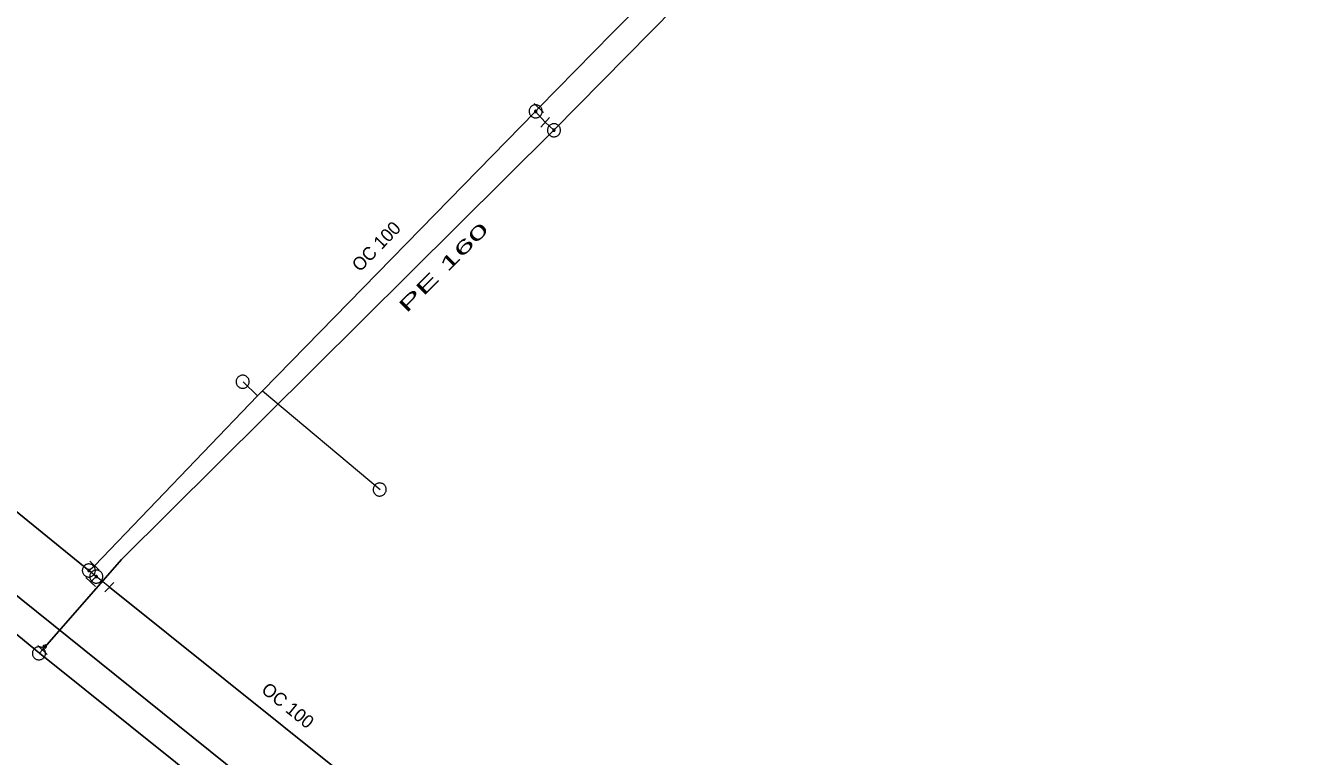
# Model space of a CAD drawing. Extents: x -807203 to -805207, y -993656 to -992505.
# Drawn here: x -806438 to -806339.8, y -992895 to -992839.2 of the extents above; entities that cross this region are included whole.
import ezdxf

# ---------------------------------------------------------------- set-up
doc = ezdxf.new("R2010")
doc.units = 0
doc.header["$LTSCALE"] = 0.4
for name, color, linetype, lineweight in [('1', 7, 'Continuous', 13), ('13', 7, 'Continuous', 13), ('14', 7, 'Continuous', 25), ('17', 7, 'Continuous', 25), ('23', 7, 'Continuous', 13), ('34', 7, 'Continuous', 13), ('47', 7, 'Continuous', 13)]:
    doc.layers.add(name, color=color, linetype=linetype, lineweight=lineweight)

msp = doc.modelspace()

# ---------------------------------------------------------------- linework, layer by layer
at = {"layer": '13'}
for p, q in [((-806420.276, -992867.469), (-806421.386, -992866.4)), ((-806419.892, -992867.102), (-806410.923, -992874.624))]:
    msp.add_line(p, q, dxfattribs=at)
at = {"layer": '14', "lineweight": 13}
for p, q in [((-806398.804, -992845.506), (-806399.05, -992845.763)), ((-806433.161, -992880.802), (-806432.726, -992880.435)), ((-806432.592, -992881.266), (-806433.161, -992880.802)), ((-806432.592, -992881.266), (-806433.026, -992881.683)), ((-806431.594, -992882.078), (-806432.592, -992881.266)), ((-806436.941, -992887.123), (-806436.699, -992886.863))]:
    msp.add_line(p, q, dxfattribs=at)
at = {"layer": '14'}
msp.add_lwpolyline([(-806439.491, -992882.042), (-806390.48, -992921.449), (-806366.285, -992941.529), (-806350.28, -992945.949), (-806336.559, -992959.469), (-806296.91, -993006.629), (-806254.43, -993051.92)], dxfattribs=at)
at = {"layer": '17'}
for p, q in [((-806398.321, -992846.589), (-806399.05, -992845.763)), ((-806397.651, -992847.204), (-806398.321, -992846.589))]:
    msp.add_line(p, q, dxfattribs=at)
for points in [[(-806521.443, -992807.149), (-806519.338, -992810.368), (-806510.309, -992820.324), (-806509.868, -992820.798), (-806504.706, -992825.727), (-806500.491, -992829.715), (-806490.227, -992839.136), (-806481.238, -992847.311), (-806469.245, -992858.467), (-806459.171, -992867.71), (-806448.037, -992877.98), (-806436.941, -992887.123)], [(-806361.995, -992808.32), (-806393.217, -992839.791), (-806398.804, -992845.506)], [(-806397.651, -992847.204), (-806360.609, -992809.633), (-806361.818, -992808.52)], [(-806433.161, -992880.802), (-806443.471, -992872.44), (-806476.543, -992840.262)], [(-806399.05, -992845.763), (-806419.892, -992867.102), (-806420.276, -992867.469), (-806432.726, -992880.435)], [(-806436.699, -992886.863), (-806430.658, -992879.958), (-806397.651, -992847.204)], [(-806388.717, -992915.707), (-806398.552, -992908.37), (-806405.099, -992903.291), (-806431.594, -992882.078)], [(-806436.941, -992887.123), (-806426.546, -992895.427), (-806410.702, -992908.298), (-806403.285, -992914.215), (-806402.857, -992914.754), (-806391.193, -992925.692), (-806378.734, -992937.224), (-806370.048, -992945.254), (-806362.636, -992951.833), (-806355.477, -992958.243), (-806351.647, -992962.778), (-806345.155, -992970.14), (-806339.761, -992976.258), (-806328.906, -992988.261), (-806292.949, -993029.767), (-806263.022, -993062.39), (-806260.066, -993064.828)]]:
    msp.add_lwpolyline(points, dxfattribs=at)
at = {"layer": '23'}
msp.add_line((-806436.462, -992886.678), (-806436.614, -992886.553), dxfattribs=at)
for points in [[(-806421.054, -992866.743), (-806421.019, -992866.702), (-806420.99, -992866.659), (-806420.966, -992866.613), (-806420.946, -992866.564), (-806420.932, -992866.515), (-806420.923, -992866.462), (-806420.919, -992866.41), (-806420.921, -992866.359), (-806420.927, -992866.307), (-806420.94, -992866.256), (-806420.957, -992866.206), (-806420.98, -992866.158), (-806421.007, -992866.114), (-806421.039, -992866.074), (-806421.075, -992866.036), (-806421.116, -992866.001), (-806421.158, -992865.972), (-806421.206, -992865.947), (-806421.252, -992865.928), (-806421.303, -992865.912), (-806421.356, -992865.904), (-806421.408, -992865.9), (-806421.461, -992865.902), (-806421.512, -992865.908), (-806421.562, -992865.921), (-806421.612, -992865.94), (-806421.658, -992865.962), (-806421.703, -992865.99), (-806421.744, -992866.022), (-806421.782, -992866.058), (-806421.816, -992866.097), (-806421.846, -992866.141), (-806421.871, -992866.187), (-806421.891, -992866.235), (-806421.904, -992866.285), (-806421.913, -992866.337), (-806421.918, -992866.389), (-806421.916, -992866.442), (-806421.909, -992866.494)], [(-806421.206, -992865.947), (-806421.252, -992865.928), (-806421.303, -992865.912), (-806421.356, -992865.904), (-806421.408, -992865.9), (-806421.461, -992865.902), (-806421.512, -992865.908), (-806421.562, -992865.921), (-806421.612, -992865.94), (-806421.658, -992865.962), (-806421.703, -992865.99), (-806421.744, -992866.022), (-806421.782, -992866.058), (-806421.816, -992866.097), (-806421.846, -992866.141), (-806421.871, -992866.187), (-806421.891, -992866.235), (-806421.904, -992866.285), (-806421.913, -992866.337), (-806421.918, -992866.389), (-806421.916, -992866.442), (-806421.909, -992866.494), (-806421.897, -992866.544), (-806421.879, -992866.593), (-806421.857, -992866.64), (-806421.828, -992866.685), (-806421.796, -992866.726), (-806421.761, -992866.764), (-806421.72, -992866.797), (-806421.677, -992866.827), (-806421.631, -992866.852), (-806421.582, -992866.871), (-806421.532, -992866.886), (-806421.481, -992866.896), (-806421.428, -992866.899), (-806421.377, -992866.898), (-806421.325, -992866.891), (-806421.273, -992866.879), (-806421.224, -992866.861), (-806421.177, -992866.838)], [(-806421.909, -992866.494), (-806421.897, -992866.544), (-806421.879, -992866.593), (-806421.857, -992866.64), (-806421.828, -992866.685), (-806421.796, -992866.726), (-806421.761, -992866.764), (-806421.72, -992866.797), (-806421.677, -992866.827), (-806421.631, -992866.852), (-806421.582, -992866.871), (-806421.532, -992866.886), (-806421.481, -992866.896), (-806421.428, -992866.899), (-806421.377, -992866.898), (-806421.325, -992866.891), (-806421.273, -992866.879), (-806421.224, -992866.861), (-806421.177, -992866.838), (-806421.133, -992866.809), (-806421.092, -992866.778), (-806421.054, -992866.743), (-806421.019, -992866.702), (-806420.99, -992866.659), (-806420.966, -992866.613), (-806420.946, -992866.564), (-806420.932, -992866.515), (-806420.923, -992866.462), (-806420.919, -992866.41), (-806420.921, -992866.359), (-806420.927, -992866.307), (-806420.94, -992866.256), (-806420.957, -992866.206), (-806420.98, -992866.158), (-806421.007, -992866.114), (-806421.039, -992866.074), (-806421.075, -992866.036), (-806421.116, -992866.001), (-806421.158, -992865.972), (-806421.206, -992865.947)], [(-806421.177, -992866.838), (-806421.133, -992866.809), (-806421.092, -992866.778), (-806421.054, -992866.743)], [(-806410.591, -992874.967), (-806410.556, -992874.926), (-806410.527, -992874.883), (-806410.503, -992874.837), (-806410.483, -992874.788), (-806410.469, -992874.739), (-806410.46, -992874.686), (-806410.456, -992874.634), (-806410.458, -992874.583), (-806410.464, -992874.531), (-806410.477, -992874.48), (-806410.494, -992874.43), (-806410.517, -992874.382), (-806410.544, -992874.338), (-806410.576, -992874.298), (-806410.612, -992874.26), (-806410.653, -992874.225), (-806410.695, -992874.196), (-806410.743, -992874.171), (-806410.789, -992874.152), (-806410.84, -992874.136), (-806410.893, -992874.128), (-806410.945, -992874.124), (-806410.998, -992874.126), (-806411.049, -992874.132), (-806411.099, -992874.145), (-806411.149, -992874.164), (-806411.195, -992874.186), (-806411.24, -992874.214), (-806411.281, -992874.246), (-806411.319, -992874.282), (-806411.353, -992874.321), (-806411.383, -992874.365), (-806411.408, -992874.411), (-806411.428, -992874.459), (-806411.441, -992874.509), (-806411.45, -992874.561), (-806411.455, -992874.613), (-806411.453, -992874.666), (-806411.446, -992874.718)], [(-806410.743, -992874.171), (-806410.789, -992874.152), (-806410.84, -992874.136), (-806410.893, -992874.128), (-806410.945, -992874.124), (-806410.998, -992874.126), (-806411.049, -992874.132), (-806411.099, -992874.145), (-806411.149, -992874.164), (-806411.195, -992874.186), (-806411.24, -992874.214), (-806411.281, -992874.246), (-806411.319, -992874.282), (-806411.353, -992874.321), (-806411.383, -992874.365), (-806411.408, -992874.411), (-806411.428, -992874.459), (-806411.441, -992874.509), (-806411.45, -992874.561), (-806411.455, -992874.613), (-806411.453, -992874.666), (-806411.446, -992874.718), (-806411.434, -992874.768), (-806411.416, -992874.817), (-806411.394, -992874.864), (-806411.365, -992874.909), (-806411.333, -992874.95), (-806411.298, -992874.988), (-806411.257, -992875.021), (-806411.214, -992875.051), (-806411.168, -992875.076), (-806411.119, -992875.095), (-806411.069, -992875.11), (-806411.018, -992875.12), (-806410.965, -992875.123), (-806410.914, -992875.122), (-806410.862, -992875.115), (-806410.81, -992875.103), (-806410.761, -992875.085), (-806410.714, -992875.062)], [(-806411.446, -992874.718), (-806411.434, -992874.768), (-806411.416, -992874.817), (-806411.394, -992874.864), (-806411.365, -992874.909), (-806411.333, -992874.95), (-806411.298, -992874.988), (-806411.257, -992875.021), (-806411.214, -992875.051), (-806411.168, -992875.076), (-806411.119, -992875.095), (-806411.069, -992875.11), (-806411.018, -992875.12), (-806410.965, -992875.123), (-806410.914, -992875.122), (-806410.862, -992875.115), (-806410.81, -992875.103), (-806410.761, -992875.085), (-806410.714, -992875.062), (-806410.67, -992875.033), (-806410.629, -992875.002), (-806410.591, -992874.967), (-806410.556, -992874.926), (-806410.527, -992874.883), (-806410.503, -992874.837), (-806410.483, -992874.788), (-806410.469, -992874.739), (-806410.46, -992874.686), (-806410.456, -992874.634), (-806410.458, -992874.583), (-806410.464, -992874.531), (-806410.477, -992874.48), (-806410.494, -992874.43), (-806410.517, -992874.382), (-806410.544, -992874.338), (-806410.576, -992874.298), (-806410.612, -992874.26), (-806410.653, -992874.225), (-806410.695, -992874.196), (-806410.743, -992874.171)], [(-806410.714, -992875.062), (-806410.67, -992875.033), (-806410.629, -992875.002), (-806410.591, -992874.967)], [(-806436.584, -992887.439), (-806436.552, -992887.397), (-806436.526, -992887.351), (-806436.506, -992887.303), (-806436.49, -992887.253), (-806436.479, -992887.203), (-806436.474, -992887.15), (-806436.474, -992887.098), (-806436.48, -992887.046), (-806436.491, -992886.995), (-806436.507, -992886.945), (-806436.528, -992886.897), (-806436.555, -992886.851), (-806436.585, -992886.809), (-806436.62, -992886.772), (-806436.658, -992886.736), (-806436.703, -992886.705), (-806436.746, -992886.679), (-806436.796, -992886.658), (-806436.844, -992886.642), (-806436.895, -992886.63), (-806436.949, -992886.626), (-806437.001, -992886.626), (-806437.053, -992886.632), (-806437.104, -992886.642), (-806437.153, -992886.659), (-806437.201, -992886.681), (-806437.246, -992886.707), (-806437.288, -992886.738), (-806437.327, -992886.774), (-806437.362, -992886.812), (-806437.393, -992886.854), (-806437.419, -992886.9), (-806437.441, -992886.948), (-806437.457, -992886.997), (-806437.466, -992887.048), (-806437.472, -992887.1), (-806437.472, -992887.153), (-806437.466, -992887.206), (-806437.455, -992887.256)], [(-806436.796, -992886.658), (-806436.844, -992886.642), (-806436.895, -992886.63), (-806436.949, -992886.626), (-806437.001, -992886.626), (-806437.053, -992886.632), (-806437.104, -992886.642), (-806437.153, -992886.659), (-806437.201, -992886.681), (-806437.246, -992886.707), (-806437.288, -992886.738), (-806437.327, -992886.774), (-806437.362, -992886.812), (-806437.393, -992886.854), (-806437.419, -992886.9), (-806437.441, -992886.948), (-806437.457, -992886.997), (-806437.466, -992887.048), (-806437.472, -992887.1), (-806437.472, -992887.153), (-806437.466, -992887.206), (-806437.455, -992887.256), (-806437.44, -992887.305), (-806437.417, -992887.354), (-806437.392, -992887.399), (-806437.36, -992887.441), (-806437.325, -992887.479), (-806437.287, -992887.514), (-806437.244, -992887.544), (-806437.199, -992887.571), (-806437.151, -992887.593), (-806437.101, -992887.608), (-806437.049, -992887.619), (-806436.998, -992887.625), (-806436.945, -992887.623), (-806436.894, -992887.619), (-806436.843, -992887.608), (-806436.792, -992887.592), (-806436.744, -992887.57), (-806436.699, -992887.544)], [(-806437.455, -992887.256), (-806437.44, -992887.305), (-806437.417, -992887.354), (-806437.392, -992887.399), (-806437.36, -992887.441), (-806437.325, -992887.479), (-806437.287, -992887.514), (-806437.244, -992887.544), (-806437.199, -992887.571), (-806437.151, -992887.593), (-806437.101, -992887.608), (-806437.049, -992887.619), (-806436.998, -992887.625), (-806436.945, -992887.623), (-806436.894, -992887.619), (-806436.843, -992887.608), (-806436.792, -992887.592), (-806436.744, -992887.57), (-806436.699, -992887.544), (-806436.658, -992887.512), (-806436.619, -992887.478), (-806436.584, -992887.439), (-806436.552, -992887.397), (-806436.526, -992887.351), (-806436.506, -992887.303), (-806436.49, -992887.253), (-806436.479, -992887.203), (-806436.474, -992887.15), (-806436.474, -992887.098), (-806436.48, -992887.046), (-806436.491, -992886.995), (-806436.507, -992886.945), (-806436.528, -992886.897), (-806436.555, -992886.851), (-806436.585, -992886.809), (-806436.62, -992886.772), (-806436.658, -992886.736), (-806436.703, -992886.705), (-806436.746, -992886.679), (-806436.796, -992886.658)], [(-806436.675, -992886.628), (-806436.581, -992886.513), (-806436.408, -992886.459), (-806436.429, -992886.637), (-806436.524, -992886.752)], [(-806436.699, -992887.544), (-806436.658, -992887.512), (-806436.619, -992887.478), (-806436.584, -992887.439)]]:
    msp.add_lwpolyline(points, dxfattribs=at)
at = {"layer": '34'}
for p, q in [((-806398.446, -992845.855), (-806399.161, -992845.156)), ((-806398.658, -992846.957), (-806397.982, -992846.221)), ((-806433.087, -992880.089), (-806432.365, -992880.781)), ((-806432.664, -992882.028), (-806433.386, -992881.336)), ((-806431.939, -992882.439), (-806431.247, -992881.717)), ((-806437.065, -992886.522), (-806436.333, -992887.203))]:
    msp.add_line(p, q, dxfattribs=at)
at = {"layer": '47'}
for points in [[(-806399.399, -992846.12), (-806399.36, -992846.154), (-806399.317, -992846.185), (-806399.271, -992846.21), (-806399.224, -992846.231), (-806399.173, -992846.247), (-806399.121, -992846.257), (-806399.07, -992846.261), (-806399.017, -992846.261), (-806398.966, -992846.255), (-806398.914, -992846.244), (-806398.864, -992846.227), (-806398.817, -992846.205), (-806398.772, -992846.179), (-806398.73, -992846.147), (-806398.692, -992846.112), (-806398.658, -992846.073), (-806398.627, -992846.03), (-806398.601, -992845.984), (-806398.581, -992845.937), (-806398.565, -992845.886), (-806398.555, -992845.834), (-806398.55, -992845.782), (-806398.551, -992845.73), (-806398.556, -992845.678), (-806398.568, -992845.627), (-806398.585, -992845.577), (-806398.607, -992845.53), (-806398.633, -992845.485), (-806398.665, -992845.443), (-806398.7, -992845.405), (-806398.739, -992845.371), (-806398.782, -992845.34), (-806398.828, -992845.314), (-806398.875, -992845.294), (-806398.926, -992845.278), (-806398.977, -992845.267), (-806399.029, -992845.262), (-806399.082, -992845.263), (-806399.134, -992845.269), (-806399.185, -992845.281), (-806399.235, -992845.298), (-806399.282, -992845.319), (-806399.327, -992845.346), (-806399.369, -992845.378), (-806399.407, -992845.413), (-806399.441, -992845.452), (-806399.472, -992845.495), (-806399.498, -992845.54), (-806399.518, -992845.588), (-806399.534, -992845.639), (-806399.545, -992845.69), (-806399.549, -992845.742), (-806399.548, -992845.794), (-806399.542, -992845.846), (-806399.531, -992845.898), (-806399.514, -992845.948), (-806399.492, -992845.994), (-806399.466, -992846.04), (-806399.434, -992846.082)], [(-806399.107, -992845.821), (-806399.1, -992845.827), (-806399.093, -992845.832), (-806399.086, -992845.836), (-806399.078, -992845.839), (-806399.07, -992845.842), (-806399.061, -992845.843), (-806399.053, -992845.845), (-806399.044, -992845.844), (-806399.036, -992845.843), (-806399.027, -992845.841), (-806399.019, -992845.839), (-806399.011, -992845.835), (-806399.004, -992845.831), (-806398.997, -992845.826), (-806398.991, -992845.82), (-806398.985, -992845.813), (-806398.98, -992845.806), (-806398.976, -992845.799), (-806398.973, -992845.791), (-806398.97, -992845.783), (-806398.969, -992845.774), (-806398.967, -992845.766), (-806398.968, -992845.757), (-806398.968, -992845.748), (-806398.971, -992845.74), (-806398.973, -992845.732), (-806398.977, -992845.724), (-806398.981, -992845.717), (-806398.986, -992845.71), (-806398.992, -992845.704), (-806398.999, -992845.698), (-806399.006, -992845.693), (-806399.013, -992845.689), (-806399.021, -992845.686), (-806399.029, -992845.683), (-806399.037, -992845.681), (-806399.046, -992845.68), (-806399.055, -992845.681), (-806399.064, -992845.681), (-806399.072, -992845.684), (-806399.08, -992845.686), (-806399.088, -992845.69), (-806399.095, -992845.694), (-806399.102, -992845.699), (-806399.108, -992845.705), (-806399.114, -992845.712), (-806399.119, -992845.719), (-806399.123, -992845.726), (-806399.126, -992845.734), (-806399.129, -992845.742), (-806399.131, -992845.75), (-806399.132, -992845.759), (-806399.131, -992845.768), (-806399.13, -992845.776), (-806399.128, -992845.785), (-806399.126, -992845.793), (-806399.122, -992845.801), (-806399.118, -992845.808), (-806399.113, -992845.815)], [(-806397.296, -992846.851), (-806397.334, -992846.817), (-806397.377, -992846.785), (-806397.422, -992846.76), (-806397.469, -992846.738), (-806397.519, -992846.721), (-806397.571, -992846.71), (-806397.622, -992846.705), (-806397.675, -992846.705), (-806397.726, -992846.71), (-806397.778, -992846.72), (-806397.828, -992846.736), (-806397.876, -992846.758), (-806397.921, -992846.783), (-806397.964, -992846.814), (-806398.003, -992846.849), (-806398.037, -992846.887), (-806398.069, -992846.93), (-806398.095, -992846.976), (-806398.116, -992847.022), (-806398.133, -992847.072), (-806398.144, -992847.124), (-806398.15, -992847.176), (-806398.15, -992847.228), (-806398.145, -992847.28), (-806398.134, -992847.331), (-806398.118, -992847.381), (-806398.097, -992847.429), (-806398.071, -992847.474), (-806398.04, -992847.517), (-806398.005, -992847.556), (-806397.967, -992847.59), (-806397.924, -992847.622), (-806397.879, -992847.649), (-806397.832, -992847.669), (-806397.782, -992847.686), (-806397.731, -992847.697), (-806397.679, -992847.703), (-806397.626, -992847.704), (-806397.574, -992847.698), (-806397.523, -992847.687), (-806397.473, -992847.671), (-806397.425, -992847.651), (-806397.38, -992847.624), (-806397.337, -992847.593), (-806397.298, -992847.558), (-806397.264, -992847.52), (-806397.232, -992847.477), (-806397.206, -992847.433), (-806397.185, -992847.385), (-806397.168, -992847.335), (-806397.157, -992847.284), (-806397.151, -992847.232), (-806397.151, -992847.18), (-806397.157, -992847.128), (-806397.167, -992847.076), (-806397.183, -992847.026), (-806397.204, -992846.979), (-806397.23, -992846.933), (-806397.261, -992846.89)], [(-806397.592, -992847.146), (-806397.599, -992847.139), (-806397.606, -992847.135), (-806397.613, -992847.131), (-806397.621, -992847.127), (-806397.629, -992847.124), (-806397.637, -992847.123), (-806397.646, -992847.121), (-806397.654, -992847.121), (-806397.663, -992847.123), (-806397.671, -992847.124), (-806397.68, -992847.127), (-806397.688, -992847.131), (-806397.695, -992847.135), (-806397.702, -992847.139), (-806397.708, -992847.145), (-806397.715, -992847.152), (-806397.719, -992847.159), (-806397.723, -992847.166), (-806397.727, -992847.174), (-806397.73, -992847.182), (-806397.731, -992847.19), (-806397.733, -992847.199), (-806397.733, -992847.207), (-806397.732, -992847.217), (-806397.73, -992847.224), (-806397.727, -992847.233), (-806397.723, -992847.241), (-806397.719, -992847.248), (-806397.715, -992847.255), (-806397.709, -992847.261), (-806397.702, -992847.268), (-806397.695, -992847.272), (-806397.688, -992847.276), (-806397.68, -992847.28), (-806397.672, -992847.283), (-806397.664, -992847.285), (-806397.655, -992847.286), (-806397.647, -992847.286), (-806397.637, -992847.285), (-806397.63, -992847.283), (-806397.621, -992847.28), (-806397.613, -992847.276), (-806397.606, -992847.272), (-806397.599, -992847.268), (-806397.593, -992847.262), (-806397.586, -992847.255), (-806397.582, -992847.248), (-806397.578, -992847.241), (-806397.574, -992847.233), (-806397.571, -992847.225), (-806397.569, -992847.217), (-806397.568, -992847.208), (-806397.568, -992847.2), (-806397.57, -992847.191), (-806397.571, -992847.183), (-806397.574, -992847.174), (-806397.578, -992847.166), (-806397.582, -992847.159), (-806397.586, -992847.152)], [(-806432.773, -992881.117), (-806432.742, -992881.075), (-806432.716, -992881.029), (-806432.695, -992880.982), (-806432.678, -992880.932), (-806432.667, -992880.881), (-806432.662, -992880.828), (-806432.662, -992880.777), (-806432.667, -992880.725), (-806432.677, -992880.674), (-806432.693, -992880.623), (-806432.715, -992880.575), (-806432.741, -992880.53), (-806432.771, -992880.488), (-806432.806, -992880.449), (-806432.845, -992880.414), (-806432.887, -992880.383), (-806432.933, -992880.357), (-806432.981, -992880.335), (-806433.03, -992880.319), (-806433.081, -992880.308), (-806433.134, -992880.303), (-806433.186, -992880.302), (-806433.238, -992880.308), (-806433.289, -992880.318), (-806433.339, -992880.334), (-806433.387, -992880.356), (-806433.433, -992880.382), (-806433.474, -992880.412), (-806433.513, -992880.447), (-806433.548, -992880.486), (-806433.579, -992880.528), (-806433.605, -992880.574), (-806433.628, -992880.621), (-806433.643, -992880.671), (-806433.654, -992880.722), (-806433.66, -992880.774), (-806433.66, -992880.827), (-806433.655, -992880.879), (-806433.644, -992880.93), (-806433.628, -992880.98), (-806433.606, -992881.028), (-806433.581, -992881.073), (-806433.55, -992881.115), (-806433.515, -992881.154), (-806433.476, -992881.189), (-806433.434, -992881.22), (-806433.388, -992881.246), (-806433.341, -992881.268), (-806433.291, -992881.284), (-806433.24, -992881.295), (-806433.188, -992881.301), (-806433.136, -992881.301), (-806433.084, -992881.296), (-806433.033, -992881.285), (-806432.982, -992881.269), (-806432.934, -992881.247), (-806432.89, -992881.222), (-806432.847, -992881.191), (-806432.808, -992881.156)], [(-806433.097, -992880.853), (-806433.091, -992880.846), (-806433.088, -992880.839), (-806433.084, -992880.831), (-806433.081, -992880.823), (-806433.08, -992880.815), (-806433.079, -992880.806), (-806433.078, -992880.797), (-806433.079, -992880.789), (-806433.082, -992880.781), (-806433.084, -992880.772), (-806433.088, -992880.764), (-806433.092, -992880.757), (-806433.097, -992880.75), (-806433.102, -992880.744), (-806433.109, -992880.738), (-806433.116, -992880.732), (-806433.123, -992880.729), (-806433.131, -992880.725), (-806433.139, -992880.722), (-806433.147, -992880.721), (-806433.156, -992880.72), (-806433.165, -992880.719), (-806433.173, -992880.72), (-806433.182, -992880.722), (-806433.19, -992880.725), (-806433.198, -992880.729), (-806433.205, -992880.733), (-806433.212, -992880.738), (-806433.218, -992880.743), (-806433.224, -992880.75), (-806433.23, -992880.757), (-806433.233, -992880.764), (-806433.237, -992880.772), (-806433.24, -992880.78), (-806433.241, -992880.788), (-806433.243, -992880.796), (-806433.243, -992880.806), (-806433.242, -992880.814), (-806433.24, -992880.823), (-806433.237, -992880.831), (-806433.233, -992880.839), (-806433.229, -992880.846), (-806433.224, -992880.853), (-806433.219, -992880.859), (-806433.212, -992880.865), (-806433.205, -992880.871), (-806433.198, -992880.874), (-806433.19, -992880.878), (-806433.182, -992880.881), (-806433.174, -992880.882), (-806433.166, -992880.884), (-806433.156, -992880.884), (-806433.148, -992880.883), (-806433.14, -992880.88), (-806433.131, -992880.878), (-806433.123, -992880.874), (-806433.116, -992880.87), (-806433.109, -992880.865), (-806433.103, -992880.86)], [(-806432.204, -992881.581), (-806432.173, -992881.539), (-806432.147, -992881.493), (-806432.126, -992881.446), (-806432.109, -992881.396), (-806432.098, -992881.345), (-806432.093, -992881.292), (-806432.093, -992881.241), (-806432.098, -992881.189), (-806432.108, -992881.138), (-806432.124, -992881.087), (-806432.146, -992881.039), (-806432.172, -992880.994), (-806432.202, -992880.952), (-806432.237, -992880.913), (-806432.276, -992880.878), (-806432.318, -992880.847), (-806432.364, -992880.821), (-806432.412, -992880.799), (-806432.461, -992880.783), (-806432.512, -992880.772), (-806432.565, -992880.767), (-806432.617, -992880.766), (-806432.669, -992880.772), (-806432.72, -992880.782), (-806432.77, -992880.798), (-806432.818, -992880.82), (-806432.864, -992880.846), (-806432.905, -992880.876), (-806432.944, -992880.911), (-806432.979, -992880.95), (-806433.01, -992880.992), (-806433.036, -992881.038), (-806433.059, -992881.085), (-806433.074, -992881.135), (-806433.085, -992881.186), (-806433.091, -992881.238), (-806433.091, -992881.291), (-806433.086, -992881.343), (-806433.075, -992881.394), (-806433.059, -992881.444), (-806433.037, -992881.492), (-806433.012, -992881.537), (-806432.981, -992881.579), (-806432.946, -992881.618), (-806432.907, -992881.653), (-806432.865, -992881.684), (-806432.819, -992881.71), (-806432.772, -992881.732), (-806432.722, -992881.748), (-806432.671, -992881.759), (-806432.619, -992881.765), (-806432.567, -992881.765), (-806432.515, -992881.76), (-806432.464, -992881.749), (-806432.413, -992881.733), (-806432.365, -992881.711), (-806432.321, -992881.686), (-806432.278, -992881.655), (-806432.239, -992881.62)], [(-806432.528, -992881.317), (-806432.522, -992881.31), (-806432.519, -992881.303), (-806432.515, -992881.295), (-806432.512, -992881.287), (-806432.511, -992881.279), (-806432.51, -992881.27), (-806432.509, -992881.261), (-806432.51, -992881.253), (-806432.513, -992881.245), (-806432.515, -992881.236), (-806432.519, -992881.228), (-806432.523, -992881.221), (-806432.528, -992881.214), (-806432.533, -992881.208), (-806432.54, -992881.202), (-806432.547, -992881.196), (-806432.554, -992881.193), (-806432.562, -992881.189), (-806432.57, -992881.186), (-806432.578, -992881.185), (-806432.587, -992881.184), (-806432.596, -992881.183), (-806432.604, -992881.184), (-806432.613, -992881.186), (-806432.621, -992881.189), (-806432.629, -992881.193), (-806432.636, -992881.197), (-806432.643, -992881.202), (-806432.649, -992881.207), (-806432.655, -992881.214), (-806432.661, -992881.221), (-806432.664, -992881.228), (-806432.668, -992881.236), (-806432.671, -992881.244), (-806432.672, -992881.252), (-806432.674, -992881.26), (-806432.674, -992881.27), (-806432.673, -992881.278), (-806432.671, -992881.287), (-806432.668, -992881.295), (-806432.664, -992881.303), (-806432.66, -992881.31), (-806432.655, -992881.317), (-806432.65, -992881.323), (-806432.643, -992881.329), (-806432.636, -992881.335), (-806432.629, -992881.338), (-806432.621, -992881.342), (-806432.613, -992881.345), (-806432.605, -992881.346), (-806432.597, -992881.348), (-806432.587, -992881.348), (-806432.579, -992881.347), (-806432.571, -992881.344), (-806432.562, -992881.342), (-806432.554, -992881.338), (-806432.547, -992881.334), (-806432.54, -992881.329), (-806432.534, -992881.324)]]:
    msp.add_lwpolyline(points, close=True, dxfattribs=at)

# ---------------------------------------------------------------- texts
at = {"layer": '1'}
for rotation, p in [(46, (-806412.465, -992858.071)), (321, (-806420.072, -992890.04))]:
    msp.add_text('OC 100', height=1, rotation=rotation, dxfattribs=at).set_placement(p)
at = {"layer": '1', "width": 2.05}
msp.add_text('PE 160', height=1, rotation=45, dxfattribs=at).set_placement((-806408.915, -992861.204))

doc.saveas('drawing.dxf')
